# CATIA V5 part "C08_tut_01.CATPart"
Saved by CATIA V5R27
Part number: Part1
Bounding box of the stored display mesh (mm): x -175 to 175, y -250 to 250, z -8 to 100
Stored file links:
  E:\_Deepak\2017_Deepak\CATIA\Resources\Tutorial Files\Tutorials\c08_catia_v5_6r2016_tut\C08_tut_01.CATPart
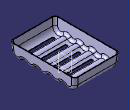
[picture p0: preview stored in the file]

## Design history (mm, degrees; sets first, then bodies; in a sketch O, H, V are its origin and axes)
Body1 (main body)
  Sketch1 on yz-plane, origin (0, 0, 0), H (0, 1, 0), V (0, 0, 1)
    point P1 (-250, 0)
    line L1 (-250, 0) -> (250, 0)
    line L2 (250, 0) -> (250, 100)
    line L3 (250, 100) -> (-250, 100)
    line L4 (-250, 100) -> (-250, 0)
    length L3 = 500
    length L2 = 100
    distance V L2 = 250
    coincidence: P1 H
    horizontal: L1 H, L3 H
    vertical: L2 V, L4 V
  Pad1: profile Sketch1, direction (1, 0, 0), length 175, mirrored extent
  Draft1: Angle -5, Neutral face of Pad1 from Sketch1.L3, PullDir face of Pad1 from Sketch1.L3
  Sketch2 on yz-plane, origin (0, 0, 0), H (0, 1, 0), V (0, 0, 1)
    arc A1 centre (-195.4346, 50) radius 50 from (-245.2443, 45.6422) to (-162.8621, 12.0654) ccw
    reference projected line E1 (-241.2511, 0) -> (-250, 100) from edge [end face of Pad1 | face of Pad1 from Sketch1.L4]
    reference projected line E2 (241.2511, 0) -> (-241.2511, 0) from edge [end face of Pad1 | face of Pad1 from Sketch1.L1]
    arc A2 centre (195.4346, 50) radius 50 from (162.8622, 12.0653) to (245.2443, 45.6422) ccw
    reference projected line E3 (250, 100) -> (241.2511, 0) from edge [end face of Pad1 | face of Pad1 from Sketch1.L2]
    reference projected line E4 (241.2511, 0) -> (-241.2511, 0) from edge [end face of Pad1 | face of Pad1 from Sketch1.L1]
    point P3 (97.7173, 50)
    point P4 (0, 50)
    point P5 (-97.7173, 50)
    construction line L1 (195.4346, 50) -> (-195.4346, 50)
    point P7 (-48.8586, -6.902)
    projected line E5 (250, 100) -> (241.2511, 0) from edge [end face of Pad1 | face of Pad1 from Sketch1.L2]
    projected line E6 (-241.2511, 0) -> (-250, 100) from edge [end face of Pad1 | face of Pad1 from Sketch1.L4]
    arc A3 centre (97.7173, 50) radius 50 from (65.1449, 12.0653) to (130.2898, 12.0654) ccw
    arc A4 centre (0, 50) radius 50 from (-32.5724, 12.0653) to (32.5725, 12.0654) ccw
    arc A5 centre (-97.7173, 50) radius 50 from (-130.2897, 12.0653) to (-65.1448, 12.0654) ccw
    point P23 (-245.2443, 45.6422)
    arc A6 centre (-146.5759, -6.902) radius 25 from (-130.2897, 12.0653) to (-162.8621, 12.0654) ccw
    arc A7 centre (-48.8586, -6.902) radius 25 from (-32.5724, 12.0653) to (-65.1448, 12.0654) ccw
    arc A8 centre (48.8586, -6.902) radius 25 from (65.1449, 12.0653) to (32.5725, 12.0654) ccw
    arc A9 centre (146.5759, -6.902) radius 25 from (162.8622, 12.0653) to (130.2898, 12.0654) ccw
    axis line L2 (146.5759, -6.902) -> (-146.5759, -6.902)
    line L3 (245.2443, 45.6422) -> (237.7725, -39.761)
    line L4 (-245.2443, 45.6422) -> (-237.7725, -39.761)
    line L5 (-237.7725, -39.761) -> (237.7725, -39.761)
    radius A1 = 50
    radius A6 = 25
    radius A5 = 50
    radius A7 = 25
    radius A4 = 50
    radius A8 = 25
    radius A3 = 50
    radius A9 = 25
    tangency: A1 E1, A1 E2, A2 E3, A2 E4, A6 A5, A7 A5, A6 A1, A7 A4, A8 A4, A8 A3, A3 A9, A9 A2, L3 A2, L4 A1
    horizontal: L1 H, L2 H, L5 H
    coincidence: P3 L1, P4 L1, P5 L1, P4 V, E6 P23, L2 P7
  Pocket1: profile Sketch2, direction (-1, 0, 0), through (limit type 3), opposite side length 175
  Fillet1: radius 25, on edge [face of Pocket1 | end face of Pad1]; edge [start face of Pad1 | face of Pad1 from Sketch1.L2]
  Shell1: ExtOffset 0, Face face of Pad1 from Sketch1.L3, IntOffset 5
  Sketch3 on xy-plane, origin (0, 0, 0), H (1, 0, 0), V (0, 1, 0)
    point P1 (0, 195.4)
    line L1 (105, 183.4) -> (-105, 183.4)
    line L2 (-105, 207.4) -> (105, 207.4)
    arc A1 centre (105, 195.4) radius 12 from (105, 183.4) to (105, 207.4) ccw
    point P6 (105, 195.4)
    arc A2 centre (-105, 195.4) radius 12 from (-105, 207.4) to (-105, 183.4) ccw
    point P7 (-105, 195.4)
    point P8 (-105, 207.4)
    axis line L3 (105, 195.4) -> (-105, 195.4)
    reference projected line E1 (175, 250) -> (-175, 250) from edge [face of Pad1 from Sketch1.L2 | face of Pad1 from Sketch1.L3]
    distance P6 P7 = 210
    distance V P7 = 105
    distance L2 L1 = 24
    distance E1 L3 = 54.6
    coincidence: P1 V, A2 P8
    horizontal: L1 H, L2 H, L3 H
    equidistance: L1 L2 P1
    tangency: A1 L1, A2 L2, A1 L2, L1 A2
  Pocket2: profile Sketch3, direction (0, 0, -1), through (limit type 6), opposite side length 25
  RectPattern1: of Pocket2, direction 1 instances 5, spacing 97.7, along edge [end face of Pad1 | face of Pad1 from Sketch1.L3] reversed
  Sketch4 on xy-plane, origin (0, 0, 0), H (1, 0, 0), V (0, 1, 0)
    circle A1 centre (-135, -196) radius 10
    point P1 (-135, -196)
    reference projected line E1 (-175, 250) -> (-175, -250) from edge [start face of Pad1 | face of Pad1 from Sketch1.L3]
    reference projected line E2 (-175, -250) -> (175, -250) from edge [face of Pad1 from Sketch1.L4 | face of Pad1 from Sketch1.L3]
    radius A1 = 10
    distance E1 P1 = 40
    distance P1 E2 = 54
  Pad2: profile Sketch4, direction (0, 0, 1), up to the existing solid (limit type 2), opposite side length 8
  RectPattern2: of Pad2, direction 1 instances 2, spacing 390.8, along edge [start face of Pad1 | face of Pad1 from Sketch1.L3] reversed, direction 2 instances 2, spacing 270, along edge [face of Pad1 from Sketch1.L4 | face of Pad1 from Sketch1.L3]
